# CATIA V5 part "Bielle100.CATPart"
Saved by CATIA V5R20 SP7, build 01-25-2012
Part number: Bielle100
Publications: "Demi_longueur_bielle", "Rayon_bielle", "Diam_trou_ext", "Diam_trou_int", "Hauteur_Extremite"
Bounding box of the stored display mesh (mm): x -70 to 70, y -20 to 20, z -10 to 10
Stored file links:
  D:\thinkmotion-MPB\Fait\Mettre en ligne\CIAO_2010\CIAO_2010_544_thucteau\CAO\Bielle100.CATPart
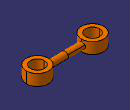
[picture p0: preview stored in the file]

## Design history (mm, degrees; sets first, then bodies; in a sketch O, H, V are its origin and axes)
Parameters
  Demi_longueur_bielle = 50 mm
  Rayon_bielle = 6 mm
  Diam_trou_ext = 40 mm
  Diam_trou_int = 25 mm {= (Diam_trou_ext+10mm) /2}
  Hauteur_Extremite = 10 mm
Body1 (main body)
  Sketch1 on xy-plane, origin (0, 0, 0), H (1, 0, 0), V (0, 1, 0)
    point P1 (-50, 0)
    line L1 (-50, 0) -> (-50, 6)
    line L2 (-50, 6) -> (0, 6)
    line L3 (0, 6) -> (0, 0)
    line L4 (0, 0) -> (-50, 0)
    length L2 = 50 {= Demi_longueur_bielle}
    length L1 = 6 {= Rayon_bielle}
    coincidence: P1 H, L3 V
    vertical: L1 V, L3 V
    horizontal: L2 H, L4 H
  Shaft1: profile Sketch1, axis Sketch1.L4, angle 360
  Sketch2 on xy-plane, origin (0, 0, 0), H (1, 0, 0), V (0, 1, 0)
    circle A1 centre (-50, 0) radius 20
    point P1 (-50, 0)
    reference projected line E1 (-50, 10) -> (-50, -10) from edge [face of Shaft1 from Sketch1.L1 | face of Shaft1 from Sketch1.L2]
    radius A1 = 20 {= Diam_trou_ext /2}
    coincidence: P1 H, P1 E1
  Pad1: profile Sketch2, direction (0, 0, 1), length 10 {= Hauteur_Extremite}, mirrored extent
  Sketch3 on end face of Pad1, origin (0, 0, 10), H (1, 0, 0), V (0, 1, 0)
    circle A1 centre (-50, 0) radius 12.5
    point P1 (-50, 0)
    reference projected circle E1 centre (-50, 0) radius 20 from edge [face of Pad1 from Sketch2.A1 | end face of Pad1]
    radius A1 = 12.5 {= Diam_trou_int /2}
    coincidence: P1 H
    concentricity: A1 E1
  Pocket1: profile Sketch3, direction (0, 0, -1), through (limit type 6)
  Mirror1: of Shaft1, Sketch1, Pad1, Sketch2, Pocket1, Sketch3, about yz-plane
Relations
  Demi_longueur_bielle = Demi_longueur_bielle (deactivated)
